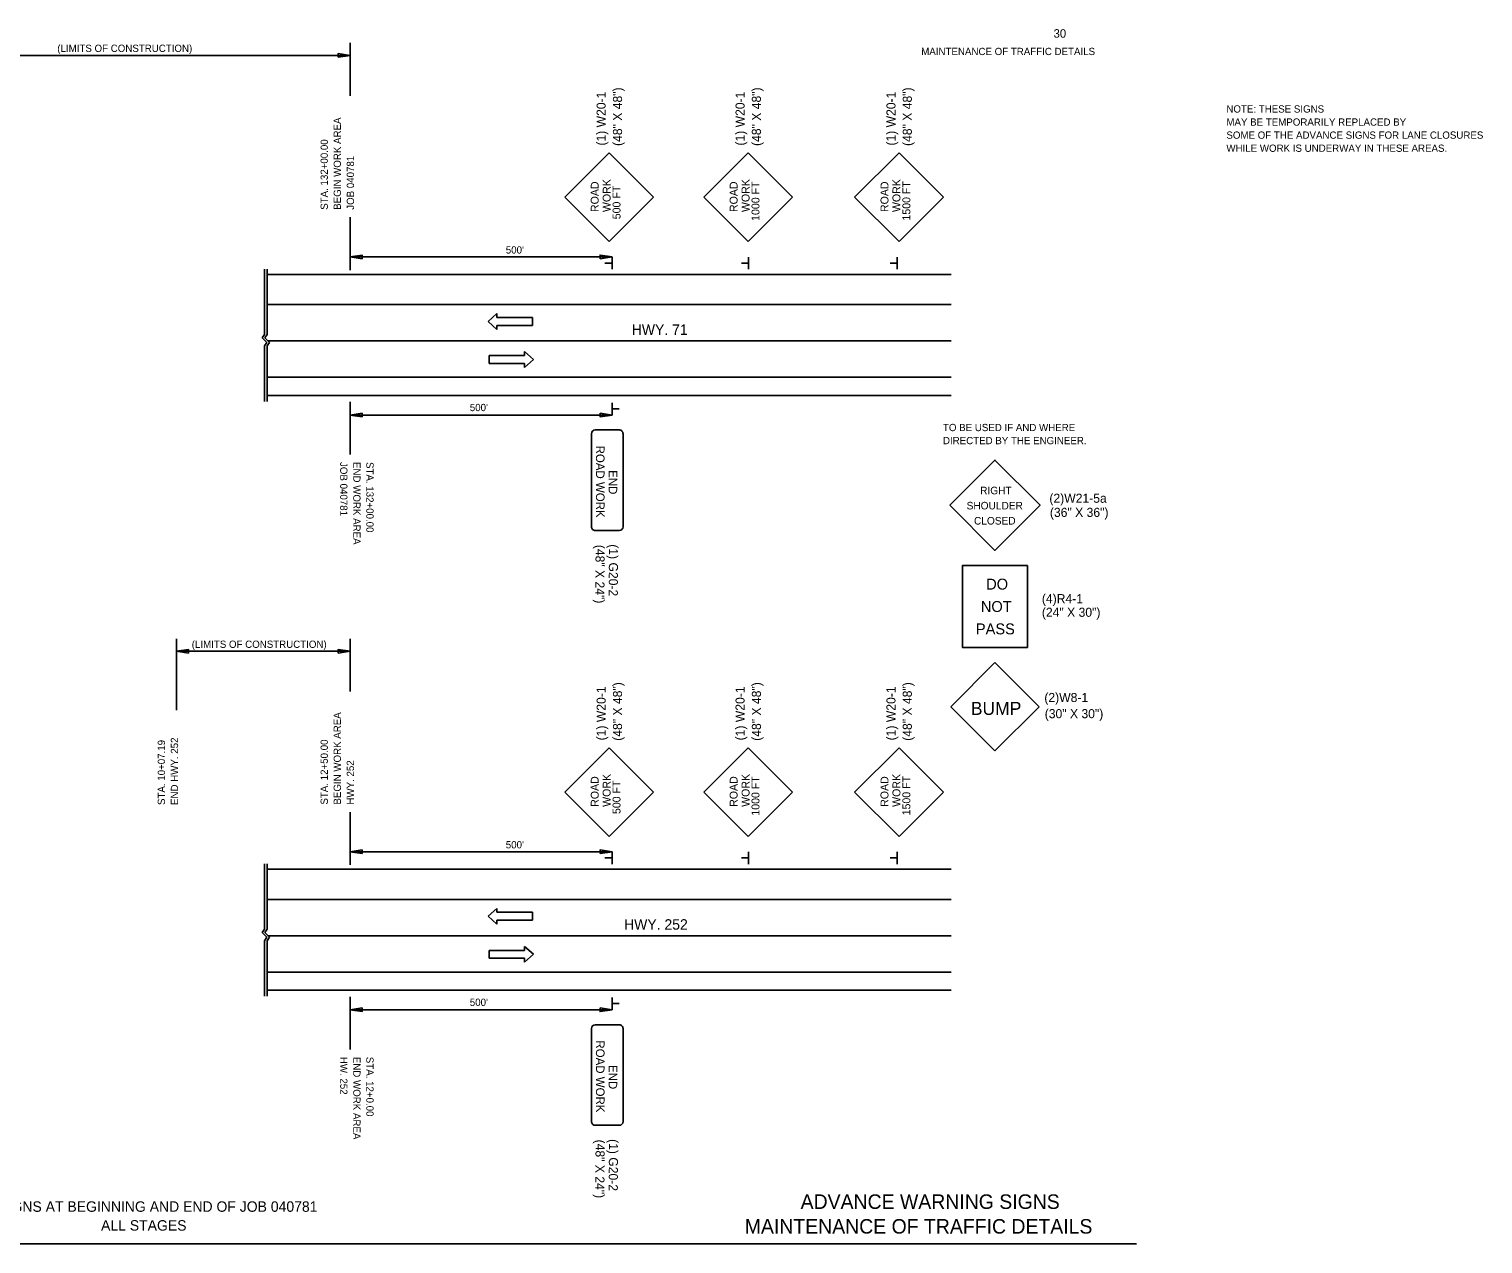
# Model space of a CAD drawing. Extents: x -900 to 1835992, y -12334 to 301063.
# Drawn here: x -428.3 to 52, y -12252.4 to -11851.1 of the extents above; entities that cross this region are included whole.
import ezdxf

# ---------------------------------------------------------------- set-up
doc = ezdxf.new("R2010")
doc.units = 0
for name, color, linetype in [('1', 7, 'Continuous'), ('Level 1', 7, 'Continuous'), ('R_MOT', 7, 'Continuous'), ('R_No Plot', 7, 'Continuous')]:
    doc.layers.add(name, color=color, linetype=linetype)

msp = doc.modelspace()

# ---------------------------------------------------------------- linework, layer by layer
at = {"layer": '1'}
for p, q in [((-322.23, -11873.11), (-322.23, -11855.67)), ((-322.23, -11859.76), (-468.81, -11859.76)), ((-322.23, -11930.7), (-322.23, -11913.26)), ((-235.67, -11926.36), (-322.23, -11926.36)), ((-235.67, -11928.41), (-238.04, -11928.41)), ((-235.67, -11926.38), (-235.67, -11930.44)), ((-190.59, -11928.41), (-192.96, -11928.41)), ((-190.59, -11926.38), (-190.59, -11930.44)), ((-141.5, -11928.41), (-143.87, -11928.41)), ((-141.5, -11926.38), (-141.5, -11930.44)), ((-350.5, -11930.37), (-350.5, -11951.95)), ((-349.63, -11930.37), (-349.63, -11951.95)), ((-123.63, -11932.11), (-349.63, -11932.11)), ((-123.63, -11942.11), (-349.63, -11942.11)), ((-351.27, -11953.09), (-350.5, -11951.95)), ((-349.73, -11954.62), (-351.27, -11953.09)), ((-350.4, -11953.09), (-349.63, -11951.95)), ((-348.86, -11954.62), (-350.4, -11953.09)), ((-350.5, -11955.77), (-349.73, -11954.62)), ((-350.5, -11955.77), (-350.5, -11974.11)), ((-349.63, -11955.77), (-348.86, -11954.62)), ((-349.63, -11955.77), (-349.63, -11974.11)), ((-123.63, -11954.11), (-349.37, -11954.11)), ((-123.63, -11966.11), (-349.63, -11966.11)), ((-123.63, -11972.11), (-349.63, -11972.11)), ((-322.23, -11974.25), (-322.23, -11991.68)), ((-235.67, -11978.58), (-235.67, -11974.51)), ((-235.67, -11976.55), (-233.31, -11976.55)), ((-322.23, -11978.58), (-235.67, -11978.58)), ((-379.62, -12076.08), (-379.62, -12052.54)), ((-379.62, -12052.54), (-379.62, -12057.79)), ((-322.18, -12069.98), (-322.18, -12052.54)), ((-322.18, -12056.63), (-379.62, -12056.63)), ((-322.23, -12127.21), (-322.23, -12109.77)), ((-235.67, -12122.87), (-322.23, -12122.87)), ((-235.67, -12124.92), (-238.04, -12124.92)), ((-235.67, -12122.89), (-235.67, -12126.95)), ((-190.59, -12124.92), (-192.96, -12124.92)), ((-190.59, -12122.89), (-190.59, -12126.95)), ((-141.5, -12124.92), (-143.87, -12124.92)), ((-141.5, -12122.89), (-141.5, -12126.95)), ((-350.5, -12126.88), (-350.5, -12148.45)), ((-349.63, -12126.88), (-349.63, -12148.45)), ((-123.63, -12128.62), (-349.63, -12128.62)), ((-123.63, -12138.62), (-349.63, -12138.62)), ((-351.27, -12149.6), (-350.5, -12148.45)), ((-349.73, -12151.13), (-351.27, -12149.6)), ((-350.4, -12149.6), (-349.63, -12148.45)), ((-348.86, -12151.13), (-350.4, -12149.6)), ((-350.5, -12152.28), (-349.73, -12151.13)), ((-350.5, -12152.28), (-350.5, -12170.62)), ((-349.63, -12152.28), (-348.86, -12151.13)), ((-349.63, -12152.28), (-349.63, -12170.62)), ((-123.63, -12150.62), (-349.37, -12150.62)), ((-123.63, -12162.62), (-349.63, -12162.62)), ((-123.63, -12168.62), (-349.63, -12168.62)), ((-322.23, -12170.76), (-322.23, -12188.19)), ((-235.67, -12175.09), (-235.67, -12171.02)), ((-235.67, -12173.06), (-233.31, -12173.06)), ((-322.23, -12175.09), (-235.67, -12175.09))]:
    msp.add_line(p, q, dxfattribs=at)
for points in [[(-326.19, -11860.36), (-322.23, -11859.76), (-326.19, -11859.16)], [(-318.27, -11926.96), (-322.23, -11926.36), (-318.27, -11925.76)], [(-239.63, -11926.96), (-235.67, -11926.36), (-239.63, -11925.76)], [(-318.27, -11977.98), (-322.23, -11978.58), (-318.27, -11979.18)], [(-239.63, -11977.98), (-235.67, -11978.58), (-239.63, -11979.18)], [(-375.66, -12057.23), (-379.62, -12056.63), (-375.66, -12056.03)], [(-326.14, -12057.23), (-322.18, -12056.63), (-326.14, -12056.03)], [(-318.27, -12123.47), (-322.23, -12122.87), (-318.27, -12122.27)], [(-239.63, -12123.47), (-235.67, -12122.87), (-239.63, -12122.27)], [(-318.27, -12174.49), (-322.23, -12175.09), (-318.27, -12175.69)], [(-239.63, -12174.49), (-235.67, -12175.09), (-239.63, -12175.69)]]:
    msp.add_lwpolyline(points, close=True, dxfattribs=at)
at = {"layer": 'Level 1'}
msp.add_line((-62.41, -12252.44), (-702.63, -12252.44), dxfattribs=at)
at = {"layer": 'R_MOT'}
for p, q in [((-236.62, -11891.99), (-251.28, -11906.65)), ((-236.62, -11891.99), (-221.98, -11906.65)), ((-190.74, -11891.99), (-205.4, -11906.65)), ((-190.74, -11891.99), (-176.09, -11906.65)), ((-140.9, -11891.99), (-155.56, -11906.65)), ((-140.9, -11891.99), (-126.25, -11906.65)), ((-251.28, -11906.65), (-236.62, -11921.31)), ((-221.98, -11906.65), (-236.62, -11921.31)), ((-205.4, -11906.65), (-190.74, -11921.31)), ((-176.09, -11906.65), (-190.74, -11921.31)), ((-155.56, -11906.65), (-140.9, -11921.31)), ((-126.25, -11906.65), (-140.9, -11921.31)), ((-276.61, -11947.68), (-273.74, -11945.06)), ((-273.74, -11950.29), (-276.61, -11947.68)), ((-273.74, -11946.37), (-273.74, -11945.06)), ((-261.98, -11946.37), (-273.74, -11946.37)), ((-261.98, -11948.98), (-261.98, -11946.37)), ((-261.98, -11948.98), (-273.74, -11948.98)), ((-273.74, -11948.98), (-273.74, -11950.29)), ((-264.57, -11958.95), (-264.57, -11957.64)), ((-261.7, -11960.25), (-264.57, -11957.64)), ((-276.33, -11958.95), (-264.57, -11958.95)), ((-276.33, -11961.56), (-276.33, -11958.95)), ((-276.33, -11961.56), (-264.57, -11961.56)), ((-264.57, -11962.87), (-261.7, -11960.25)), ((-264.57, -11961.56), (-264.57, -11962.87)), ((-242.49, -12015.49), (-242.49, -11984.78)), ((-241.24, -11983.53), (-233.31, -11983.53)), ((-232.06, -12015.49), (-232.06, -11984.78)), ((-241.24, -12016.74), (-233.31, -12016.74)), ((-123.83, -12074.99), (-109.23, -12060.39)), ((-109.23, -12060.39), (-94.64, -12074.99)), ((-123.83, -12074.99), (-109.23, -12089.58)), ((-109.23, -12089.58), (-94.64, -12074.99)), ((-236.62, -12088.5), (-251.28, -12103.16)), ((-236.62, -12088.5), (-221.98, -12103.16)), ((-190.74, -12088.5), (-205.4, -12103.16)), ((-190.74, -12088.5), (-176.09, -12103.16)), ((-140.9, -12088.5), (-155.56, -12103.16)), ((-140.9, -12088.5), (-126.25, -12103.16)), ((-251.28, -12103.16), (-236.62, -12117.82)), ((-221.98, -12103.16), (-236.62, -12117.82)), ((-205.4, -12103.16), (-190.74, -12117.82)), ((-176.09, -12103.16), (-190.74, -12117.82)), ((-155.56, -12103.16), (-140.9, -12117.82)), ((-126.25, -12103.16), (-140.9, -12117.82)), ((-276.61, -12144.19), (-273.74, -12141.57)), ((-273.74, -12146.8), (-276.61, -12144.19)), ((-273.74, -12142.88), (-273.74, -12141.57)), ((-261.98, -12142.88), (-273.74, -12142.88)), ((-261.98, -12145.49), (-261.98, -12142.88)), ((-261.98, -12145.49), (-273.74, -12145.49)), ((-273.74, -12145.49), (-273.74, -12146.8)), ((-264.57, -12155.46), (-264.57, -12154.15)), ((-261.7, -12156.76), (-264.57, -12154.15)), ((-276.33, -12155.46), (-264.57, -12155.46)), ((-276.33, -12158.07), (-276.33, -12155.46)), ((-276.33, -12158.07), (-264.57, -12158.07)), ((-264.57, -12159.38), (-261.7, -12156.76)), ((-264.57, -12158.07), (-264.57, -12159.38)), ((-242.49, -12212), (-242.49, -12181.29)), ((-241.24, -12180.04), (-233.31, -12180.04)), ((-232.06, -12212), (-232.06, -12181.29)), ((-241.24, -12213.25), (-233.31, -12213.25))]:
    msp.add_line(p, q, dxfattribs=at)
for points in [[(-124.16, -12008.39), (-109.23, -11993.46), (-94.31, -12008.39), (-109.23, -12023.31)], [(-98.49, -12028.31), (-98.49, -12055.39), (-119.98, -12055.39), (-119.98, -12028.31)]]:
    msp.add_lwpolyline(points, close=True, dxfattribs=at)
for centre, start, end in [((-241.24, -11984.78), 90.0014, 180.0003), ((-233.31, -11984.78), 0.0003, 90.0014), ((-241.24, -12015.49), 180.0003, 270.0014), ((-233.31, -12015.49), 270.0014, 0.0003), ((-241.24, -12181.29), 90.0014, 180.0003), ((-233.31, -12181.29), 0.0003, 90.0014), ((-241.24, -12212), 180.0003, 270.0014), ((-233.31, -12212), 270.0014, 0.0003)]:
    msp.add_arc(centre, 1.25, start, end, dxfattribs=at)

# ---------------------------------------------------------------- texts
at = {"layer": '1'}
for s, height, p in [('(LIMITS OF CONSTRUCTION)', 2.4, (-418.95, -11858.63)), ('MAINTENANCE OF TRAFFIC DETAILS', 2.4, (-133.57, -11859.67)), ('NOTE: THESE SIGNS', 2.4, (-32.77, -11878.67)), ('MAY BE TEMPORARILY REPLACED BY', 2.4, (-32.77, -11882.99)), ('SOME OF THE ADVANCE SIGNS FOR LANE CLOSURES', 2.4, (-32.77, -11887.31)), ('WHILE WORK IS UNDERWAY IN THESE AREAS.', 2.4, (-32.77, -11891.63)), ("500'", 2.4, (-270.8, -11925.24)), ('HWY. 71', 3.452, (-229.2, -11952.1)), ('TO BE USED IF AND WHERE', 2.4, (-126.39, -11983.91)), ('DIRECTED BY THE ENGINEER.', 2.4, (-126.39, -11988.23)), ('(LIMITS OF CONSTRUCTION)', 2.4, (-374.54, -12055.51)), ("500'", 2.4, (-270.8, -12121.75)), ('HWY. 252', 3.452, (-231.73, -12148.61)), ('ADVANCE WARNING SIGNS', 4.8, (-173.41, -12240.87)), ('ADVANCE SIGNS AT BEGINNING AND END OF JOB 040781', 3.452, (-462.04, -12241.82)), ('ALL STAGES', 3.452, (-404.49, -12248.04)), ('MAINTENANCE OF TRAFFIC DETAILS', 4.8, (-191.86, -12249.03))]:
    msp.add_text(s, height=height, dxfattribs=at).set_placement(p)
for s, rotation, p in [('BEGIN WORK AREA ', 90, (-325.26, -11910.78)), ('STA. 132+00.00', 90, (-329.58, -11910.78)), ('JOB 040781', 90, (-320.94, -11910.78)), ("500'", 360, (-282.69, -11977.3)), ('JOB 040781', 270, (-325.51, -11994.11)), ('END WORK AREA ', 270, (-321.19, -11994.11)), ('STA. 132+00.00', 270, (-316.87, -11994.11)), ('BEGIN WORK AREA ', 90, (-325.26, -12107.29)), ('STA. 10+07.19', 90, (-383.37, -12107.43)), ('END HWY. 252', 90, (-379.05, -12107.43)), ('STA. 12+50.00', 90, (-329.58, -12107.29)), ('HWY. 252', 90, (-320.94, -12107.29)), ("500'", 360, (-282.69, -12173.81)), ('HW. 252', 270, (-325.51, -12190.62)), ('END WORK AREA ', 270, (-321.19, -12190.62)), ('STA. 12+0.00', 270, (-316.87, -12190.62))]:
    msp.add_text(s, height=2.4, rotation=rotation, dxfattribs=at).set_placement(p)
at = {"layer": 'R_MOT'}
for s, height, rotation, p in [('(48" X 48")', 3, 90, (-232.4, -11889.7)), ('(48" X 48")', 3, 90, (-186.52, -11889.7)), ('(48" X 48")', 3, 90, (-136.68, -11889.7)), ('(1) W20-1', 3, 90, (-237.8, -11889.57)), ('(1) W20-1', 3, 90, (-191.91, -11889.57)), ('(1) W20-1', 3, 90, (-142.07, -11889.57)), ('ROAD', 2.613, 90.0004, (-240.12, -11911.52)), ('WORK', 2.613, 90, (-236.18, -11911.53)), ('500 FT', 2.613, 90, (-232.91, -11913.91)), ('ROAD', 2.613, 90.0004, (-194.24, -11911.52)), ('WORK', 2.613, 90, (-190.29, -11911.53)), ('1000 FT', 2.613, 90, (-187.02, -11914.44)), ('ROAD', 2.613, 90.0004, (-144.4, -11911.52)), ('WORK', 2.613, 90, (-140.45, -11911.53)), ('1500 FT', 2.613, 90, (-137.18, -11914.34)), ('ROAD WORK', 2.835, 270.0006, (-241.02, -11988.69)), ('END', 2.835, 270.0006, (-236.83, -11996.81)), ('(48" X 24")', 3, 269.6927, (-241.14, -12021.46)), ('(1) G20-2', 3, 269.6927, (-236.71, -12021.28)), ('(1) W20-1', 3, 90, (-237.8, -12086.08)), ('(48" X 48")', 3, 90, (-232.4, -12086.21)), ('(1) W20-1', 3, 90, (-191.91, -12086.08)), ('(48" X 48")', 3, 90, (-186.52, -12086.21)), ('(1) W20-1', 3, 90, (-142.07, -12086.08)), ('(48" X 48")', 3, 90, (-136.68, -12086.21)), ('WORK', 2.613, 90, (-236.18, -12108.04)), ('WORK', 2.613, 90, (-190.29, -12108.04)), ('WORK', 2.613, 90, (-140.45, -12108.04)), ('ROAD', 2.613, 90.0004, (-240.12, -12108.03)), ('500 FT', 2.613, 90, (-232.91, -12110.42)), ('ROAD', 2.613, 90.0004, (-194.24, -12108.03)), ('1000 FT', 2.613, 90, (-187.02, -12110.95)), ('ROAD', 2.613, 90.0004, (-144.4, -12108.03)), ('1500 FT', 2.613, 90, (-137.18, -12110.85)), ('ROAD WORK', 2.835, 270.0006, (-241.02, -12185.2)), ('END', 2.835, 270.0006, (-236.83, -12193.32)), ('(48" X 24")', 3, 269.6927, (-241.14, -12217.97)), ('(1) G20-2', 3, 269.6927, (-236.71, -12217.79))]:
    msp.add_text(s, height=height, rotation=rotation, dxfattribs=at).set_placement(p)
for s, height, p in [('RIGHT', 2.5, (-114.11, -12004.77)), ('(2)W21-5a', 3, (-91.24, -12007.57)), ('SHOULDER', 2.5, (-118.58, -12009.77)), ('(36" X 36")', 3, (-91.07, -12012.24)), ('CLOSED', 2.5, (-116.14, -12014.77)), ('DO', 3.605, (-112.12, -12036.26)), ('(4)R4-1', 2.999, (-93.72, -12040.75)), ('NOT', 3.605, (-113.88, -12043.65)), ('(24" X 30")', 2.9995, (-93.72, -12045.25)), ('PASS', 3.605, (-115.51, -12051.05)), ('(2)W8-1', 3.001, (-92.91, -12073.41)), ('BUMP', 4.321, (-117.19, -12077.67)), ('(30" X 30")', 3.0008, (-92.78, -12078.75))]:
    msp.add_text(s, height=height, dxfattribs=at).set_placement(p)
at = {"layer": 'R_No Plot'}
msp.add_text('30', height=2.8, dxfattribs=at).set_placement((-89.86, -11853.92))

doc.saveas('drawing.dxf')
